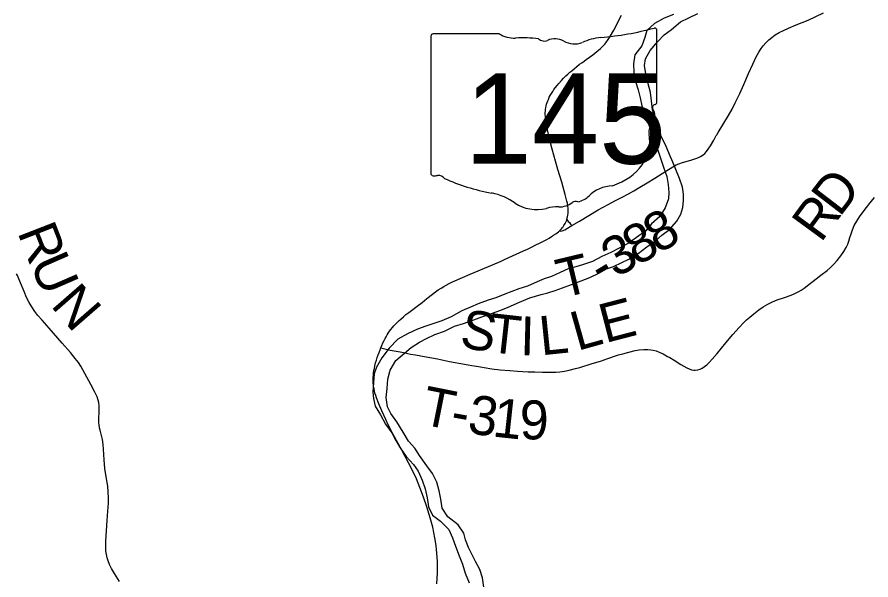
# Model space of a CAD drawing. Extents: x -10.5 to 40.6, y -3.2 to 22.
# Drawn here: x -8.513 to -7.268, y 15.194 to 16.014 of the extents above; entities that cross this region are included whole.
import ezdxf

# ---------------------------------------------------------------- set-up
doc = ezdxf.new("R2010")
doc.units = 0
for name, color, linetype in [('GM_X_Major_River', 7, 'Continuous'), ('GM_X_State_Location', 7, 'Continuous'), ('GM_X_State_Route', 7, 'Continuous'), ('GM_X_State_Shield', 7, 'Continuous'), ('GM_X_Township_Road', 7, 'Continuous'), ('GM_X_Township_Road_Text', 7, 'Continuous')]:
    doc.layers.add(name, color=color, linetype=linetype)

msp = doc.modelspace()

# ---------------------------------------------------------------- linework, layer by layer
at = {"layer": 'GM_X_Major_River'}
for points in [[(-7.5554, 16.0181), (-7.569, 16.0126), (-7.5833, 16.0052), (-7.5942, 15.9948), (-7.5971, 15.9846), (-7.6018, 15.9724), (-7.6119, 15.9593), (-7.6136, 15.9464), (-7.6134, 15.9335), (-7.611, 15.9203), (-7.607, 15.9082), (-7.6042, 15.8965), (-7.6018, 15.8851), (-7.597, 15.8719), (-7.5916, 15.8579), (-7.5872, 15.8451), (-7.5829, 15.8319), (-7.5785, 15.8202), (-7.5746, 15.8085), (-7.5699, 15.7957), (-7.5651, 15.7817), (-7.5634, 15.7703), (-7.5621, 15.7586), (-7.5628, 15.7491), (-7.5675, 15.7361), (-7.5753, 15.7235), (-7.5877, 15.7127), (-7.5959, 15.7027), (-7.6094, 15.6931), (-7.6203, 15.6853), (-7.6338, 15.678), (-7.647, 15.6709), (-7.6598, 15.6651), (-7.6738, 15.6577), (-7.6881, 15.6533), (-7.6979, 15.6501), (-7.7093, 15.647), (-7.7209, 15.6419), (-7.7334, 15.636), (-7.7439, 15.6325), (-7.7545, 15.6285), (-7.7684, 15.6219), (-7.7809, 15.6179), (-7.7911, 15.614), (-7.8016, 15.6104), (-7.8148, 15.6049), (-7.8258, 15.6014), (-7.8405, 15.5962), (-7.8518, 15.5912), (-7.8642, 15.5861), (-7.8797, 15.5771), (-7.8936, 15.5712), (-7.9053, 15.5673), (-7.9166, 15.5637), (-7.9291, 15.559), (-7.9434, 15.5524), (-7.9577, 15.5446), (-7.9704, 15.5315), (-7.9808, 15.5173), (-7.9886, 15.5039), (-7.9919, 15.494), (-7.9933, 15.4815), (-7.9942, 15.4675), (-7.9933, 15.458), (-7.9905, 15.447), (-7.9831, 15.4342), (-7.9754, 15.4207), (-7.9661, 15.4079), (-7.9603, 15.397), (-7.9541, 15.3864), (-7.9452, 15.3733), (-7.9348, 15.362), (-7.9278, 15.3519)], [(-7.9258, 15.375), (-7.9328, 15.3856), (-7.9421, 15.3961), (-7.9498, 15.4092), (-7.9591, 15.4239), (-7.968, 15.4363), (-7.9727, 15.4461), (-7.9748, 15.4594), (-7.973, 15.4727), (-7.9721, 15.4863), (-7.9689, 15.4993), (-7.9603, 15.5134), (-7.948, 15.5242), (-7.9382, 15.5323), (-7.9258, 15.5401), (-7.9156, 15.5455), (-7.9036, 15.5514), (-7.8896, 15.5565), (-7.8749, 15.5635), (-7.8617, 15.5675), (-7.8466, 15.573), (-7.8353, 15.5773), (-7.821, 15.5821), (-7.8074, 15.5868), (-7.7968, 15.5915), (-7.7803, 15.5986), (-7.7652, 15.6049), (-7.7486, 15.6096), (-7.7387, 15.612), (-7.7282, 15.6156), (-7.7176, 15.6195), (-7.7044, 15.6243), (-7.6904, 15.6298), (-7.6776, 15.6345), (-7.6644, 15.6407), (-7.6531, 15.647), (-7.643, 15.6505), (-7.6309, 15.6564), (-7.6207, 15.6614), (-7.6072, 15.6696), (-7.5944, 15.6792), (-7.5824, 15.6878), (-7.5723, 15.6962), (-7.5614, 15.7044), (-7.5506, 15.7166), (-7.545, 15.727), (-7.5421, 15.7365), (-7.5411, 15.7467), (-7.5409, 15.7562), (-7.5425, 15.7664), (-7.5469, 15.7789), (-7.5563, 15.803), (-7.5614, 15.814), (-7.5673, 15.8279), (-7.5735, 15.8404), (-7.5771, 15.8536), (-7.5814, 15.8657), (-7.5862, 15.8793), (-7.5875, 15.8921), (-7.5891, 15.9046), (-7.5931, 15.919), (-7.596, 15.9315), (-7.5976, 15.9436), (-7.5963, 15.9535), (-7.5896, 15.9657), (-7.5784, 15.9787), (-7.5691, 15.9884), (-7.5586, 15.9965), (-7.5454, 16.0073), (-7.533, 16.0131), (-7.5202, 16.0194)], [(-7.8323, 15.1828), (-7.834, 15.1965), (-7.8379, 15.2089), (-7.8445, 15.2206), (-7.8547, 15.2409), (-7.859, 15.2519), (-7.8614, 15.2617), (-7.8695, 15.2741), (-7.8848, 15.2857), (-7.893, 15.2981), (-7.8947, 15.3114), (-7.8971, 15.3235), (-7.9007, 15.3363), (-7.9069, 15.3488), (-7.9154, 15.36), (-7.9258, 15.375)], [(-7.9278, 15.3519), (-7.922, 15.3391), (-7.9176, 15.3266), (-7.9148, 15.313), (-7.9127, 15.3001), (-7.9072, 15.288), (-7.8954, 15.2791), (-7.8831, 15.2671), (-7.878, 15.2547), (-7.8733, 15.2426), (-7.8681, 15.2286), (-7.8634, 15.2165), (-7.8595, 15.2033), (-7.8536, 15.1894)]]:
    msp.add_lwpolyline(points, dxfattribs=at)
at = {"layer": 'GM_X_State_Route'}
for points in [[(-7.6543, 15.9769), (-7.653, 15.9785), (-7.6517, 15.9802), (-7.6497, 15.9833), (-7.6473, 15.987), (-7.6424, 15.9954), (-7.6393, 16.0015), (-7.6356, 16.0089), (-7.6315, 16.017)], [(-7.9005, 15.1878), (-7.8998, 15.2038), (-7.8997, 15.2149), (-7.8998, 15.2206), (-7.9001, 15.2266), (-7.901, 15.2377), (-7.9017, 15.2438), (-7.9034, 15.2548), (-7.9049, 15.2627), (-7.9067, 15.2705), (-7.9104, 15.2843), (-7.9153, 15.3003), (-7.9201, 15.3144), (-7.9253, 15.3283), (-7.9305, 15.3409), (-7.9356, 15.3522), (-7.9418, 15.3643), (-7.9518, 15.3829), (-7.965, 15.4068), (-7.9715, 15.4196), (-7.9752, 15.4274), (-7.9807, 15.4399), (-7.9852, 15.4502), (-7.9886, 15.459), (-7.9898, 15.4626), (-7.9909, 15.4661), (-7.9917, 15.4694), (-7.9923, 15.4722), (-7.9929, 15.4752), (-7.9932, 15.4777), (-7.9935, 15.4807), (-7.9936, 15.4834), (-7.9937, 15.4862), (-7.9935, 15.489), (-7.9933, 15.492), (-7.9929, 15.4952), (-7.9924, 15.4989), (-7.9918, 15.502), (-7.991, 15.5057), (-7.99, 15.5099), (-7.9889, 15.514), (-7.9877, 15.5177), (-7.9863, 15.522), (-7.985, 15.5254), (-7.9831, 15.5304), (-7.9824, 15.532), (-7.9811, 15.5352), (-7.9794, 15.5391), (-7.9777, 15.5426), (-7.9762, 15.5457), (-7.9748, 15.5482), (-7.9731, 15.551), (-7.9715, 15.5535), (-7.9697, 15.5561), (-7.9678, 15.5586), (-7.9655, 15.5615), (-7.9635, 15.5639), (-7.9611, 15.5666), (-7.9588, 15.5689), (-7.9555, 15.572), (-7.9533, 15.574), (-7.9494, 15.5773), (-7.9457, 15.5804), (-7.9415, 15.5837), (-7.9378, 15.5864), (-7.9294, 15.5929), (-7.9222, 15.5983), (-7.9155, 15.6039), (-7.9068, 15.6105), (-7.9026, 15.6136), (-7.8986, 15.6164), (-7.8943, 15.6192), (-7.8906, 15.6215), (-7.8869, 15.6235), (-7.8829, 15.6256), (-7.8778, 15.6281), (-7.8632, 15.6347), (-7.8523, 15.6394), (-7.8196, 15.653), (-7.8071, 15.6585), (-7.8008, 15.6613), (-7.7743, 15.6733), (-7.7686, 15.676), (-7.7625, 15.679), (-7.7563, 15.682), (-7.7509, 15.6848), (-7.7452, 15.6877), (-7.7404, 15.6902), (-7.7369, 15.6921), (-7.7334, 15.6942), (-7.7303, 15.6961), (-7.7273, 15.6983), (-7.7253, 15.6997), (-7.7234, 15.7013), (-7.7217, 15.7027), (-7.7203, 15.7042), (-7.7188, 15.7057), (-7.7174, 15.7073), (-7.7164, 15.7087), (-7.7153, 15.7103), (-7.7144, 15.7117), (-7.7135, 15.7134), (-7.7126, 15.7152), (-7.7118, 15.7173), (-7.7111, 15.7192), (-7.7105, 15.7214), (-7.7099, 15.7233), (-7.7096, 15.7255), (-7.7091, 15.7282), (-7.7089, 15.7306), (-7.7089, 15.7328), (-7.7091, 15.7358), (-7.7094, 15.7388), (-7.7102, 15.7429), (-7.7109, 15.746), (-7.7123, 15.7517), (-7.7134, 15.7556), (-7.7164, 15.7664), (-7.7186, 15.7735), (-7.7241, 15.792), (-7.7277, 15.8045), (-7.7323, 15.8219), (-7.7357, 15.8351), (-7.7394, 15.8501), (-7.741, 15.8574), (-7.7419, 15.863), (-7.7423, 15.8663), (-7.7424, 15.8692), (-7.7425, 15.8721), (-7.7425, 15.8749), (-7.7423, 15.8774), (-7.7421, 15.8799), (-7.7418, 15.8821), (-7.7412, 15.8849), (-7.7407, 15.8872), (-7.7399, 15.8897), (-7.739, 15.8922), (-7.738, 15.8944), (-7.7367, 15.8974), (-7.7352, 15.9), (-7.7336, 15.903), (-7.7317, 15.906), (-7.7299, 15.9086), (-7.7281, 15.9111), (-7.7251, 15.9147), (-7.7229, 15.9173), (-7.7188, 15.9218), (-7.7158, 15.9251), (-7.7123, 15.9286), (-7.7096, 15.9313), (-7.7065, 15.9341), (-7.704, 15.9362), (-7.7001, 15.9395), (-7.6963, 15.9425), (-7.6924, 15.9455), (-7.6893, 15.9477), (-7.6857, 15.9503), (-7.6827, 15.9525), (-7.6778, 15.9561), (-7.6733, 15.9594), (-7.6704, 15.9617), (-7.6675, 15.964), (-7.6647, 15.9663), (-7.6622, 15.9684), (-7.6594, 15.9711), (-7.657, 15.9736), (-7.6557, 15.9751), (-7.6543, 15.9769)]]:
    msp.add_lwpolyline(points, dxfattribs=at)
at = {"layer": 'GM_X_State_Shield'}
for p, q in [((-7.5797, 15.8903), (-7.5797, 15.995)), ((-7.9093, 15.9866), (-7.9093, 15.7865)), ((-7.8095, 15.99), (-7.9061, 15.99)), ((-7.5798, 15.8903), (-7.5797, 15.8903))]:
    msp.add_line(p, q, dxfattribs=at)
for centre, major_axis, start_param, end_param in [((-7.6971, 16.2629), (0.3495, 0), 4.814394, 5.042369), ((-7.5834, 15.9954), (0.00367, 0), 6.141152, 7.989035), ((-7.9055, 15.987), (0.00382, 0), 1.712693, 3.28349), ((-7.7866, 16.0133), (0.037, 0), 4.042523, 4.731795), ((-7.7743, 15.8777), (0.133, 0), 1.404758, 1.657858), ((-7.7441, 15.988), (0.0107, 0), 3.836095, 5.185415), ((-7.7284, 15.9649), (0.0222, 0), 0.950623, 2.079405), ((-7.6997, 15.9966), (0.0267, 0), 4.081561, 5.145723), ((-7.6525, 15.9289), (0.0703, 0), 1.699011, 2.107814), ((-7.5806, 15.8826), (0.00568, 0), 1.883978, 3.671073), ((-7.6167, 15.8694), (0.0341, 0), 5.934695, 6.695948), ((-7.5836, 15.8899), (0.00393, 0), 5.05454, 6.418171), ((-7.5666, 15.8465), (0.0248, 0), 2.387724, 3.262537), ((-7.6775, 15.8332), (0.0874, 0), 5.101752, 6.440018), ((-7.9055, 15.786), (0.00385, 0), 3.00124, 4.508301), ((-7.9049, 15.8065), (0.0294, 0), 4.665946, 4.897461), ((-7.8989, 15.7749), (0.0106, 0), 0.519207, 1.627899), ((-7.7651, 15.9547), (0.2524, 0), 4.195997, 4.488961), ((-7.6407, 15.7303), (0.0479, 0), 1.647645, 2.488434), ((-7.8403, 15.6966), (0.079, 0), 0.823519, 1.323587), ((-7.7549, 15.7739), (0.0501, 0), 4.026481, 4.996735), ((-7.7223, 15.7589), (0.0267, 0), 4.691044, 5.507374), ((-7.6981, 15.7396), (0.00752, 0), 1.147584, 2.315152), ((-7.7013, 15.7671), (0.0282, 0), 4.937069, 5.64225), ((-7.726, 15.7047), (0.0412, 0), 1.495662, 1.94098)]:
    msp.add_ellipse(centre, major_axis=major_axis, ratio=0.8, start_param=start_param, end_param=end_param, dxfattribs=at)
at = {"layer": 'GM_X_Township_Road'}
for points in [[(-7.7039, 15.7103), (-7.6928, 15.7169), (-7.679, 15.7252), (-7.6656, 15.7331), (-7.6509, 15.7412), (-7.641, 15.7464), (-7.6305, 15.7517), (-7.6213, 15.7568), (-7.6133, 15.7612), (-7.6045, 15.7663), (-7.5938, 15.7726), (-7.5827, 15.7794), (-7.5665, 15.7898), (-7.5565, 15.796), (-7.5542, 15.7974), (-7.5516, 15.7987), (-7.5476, 15.8004), (-7.5423, 15.8022), (-7.5304, 15.8057), (-7.5227, 15.8081), (-7.5192, 15.8095), (-7.516, 15.8113), (-7.5124, 15.8137), (-7.51, 15.8156), (-7.5074, 15.8183), (-7.5048, 15.8217), (-7.5017, 15.8264), (-7.4968, 15.835), (-7.4931, 15.8415), (-7.4925, 15.8425), (-7.4903, 15.8462), (-7.4752, 15.8711), (-7.47, 15.8803), (-7.4654, 15.8891), (-7.4589, 15.9031), (-7.4531, 15.9162), (-7.4462, 15.9321), (-7.4399, 15.9456), (-7.4347, 15.9562), (-7.4308, 15.9632), (-7.4274, 15.9685), (-7.4245, 15.9724), (-7.4208, 15.9767), (-7.4164, 15.9811), (-7.4122, 15.9847), (-7.4071, 15.9884), (-7.4013, 15.9919), (-7.3952, 15.995), (-7.3879, 15.9983), (-7.3764, 16.003), (-7.3591, 16.0101), (-7.3365, 16.0204)], [(-7.7466, 15.4965), (-7.7361, 15.4963), (-7.7269, 15.4966), (-7.7213, 15.4971), (-7.7145, 15.4979), (-7.7078, 15.4992), (-7.6982, 15.5017), (-7.6922, 15.5034), (-7.6739, 15.5091), (-7.6621, 15.5128), (-7.6515, 15.5164), (-7.6385, 15.5207), (-7.6355, 15.5217), (-7.6296, 15.5234), (-7.6206, 15.5258), (-7.6115, 15.5279), (-7.6054, 15.5289), (-7.5986, 15.5295), (-7.593, 15.5296), (-7.5887, 15.5292), (-7.585, 15.5286), (-7.5808, 15.5276), (-7.5762, 15.5259), (-7.5706, 15.5232), (-7.5641, 15.5196), (-7.5609, 15.5177), (-7.5545, 15.514), (-7.5446, 15.5079), (-7.5361, 15.5028), (-7.5328, 15.5012), (-7.5293, 15.4999), (-7.5257, 15.4993), (-7.5239, 15.4993), (-7.5202, 15.4997), (-7.5167, 15.5009), (-7.5139, 15.5022), (-7.5103, 15.5046), (-7.5069, 15.5074), (-7.5033, 15.5108), (-7.4991, 15.5154), (-7.4918, 15.5239), (-7.4792, 15.5392), (-7.4688, 15.5515), (-7.4597, 15.5617), (-7.4533, 15.5684), (-7.4489, 15.5727), (-7.4442, 15.5768), (-7.4385, 15.5816), (-7.4312, 15.5872), (-7.4245, 15.5917), (-7.4177, 15.5958), (-7.411, 15.5991), (-7.4041, 15.6019), (-7.3935, 15.6056), (-7.3841, 15.6088), (-7.3784, 15.6112), (-7.3729, 15.614), (-7.3691, 15.6162), (-7.365, 15.6189), (-7.3581, 15.6242), (-7.3473, 15.6326), (-7.3405, 15.6379), (-7.3315, 15.6446), (-7.3263, 15.649), (-7.3215, 15.6538), (-7.3166, 15.6595), (-7.3113, 15.6663), (-7.3071, 15.6724), (-7.3036, 15.6783), (-7.3012, 15.6833), (-7.2998, 15.6874), (-7.2981, 15.6928), (-7.2965, 15.6981), (-7.2945, 15.704), (-7.2918, 15.7103), (-7.2883, 15.7169), (-7.2842, 15.7232), (-7.2804, 15.7285), (-7.277, 15.7329), (-7.2744, 15.7362), (-7.2717, 15.7396), (-7.271, 15.7406), (-7.2625, 15.7511)], [(-7.7111, 15.7192), (-7.7089, 15.7165), (-7.7073, 15.7147), (-7.7055, 15.7123), (-7.7039, 15.7103)], [(-7.7217, 15.7027), (-7.7196, 15.7024), (-7.7179, 15.7026), (-7.7142, 15.7043), (-7.7062, 15.709), (-7.7039, 15.7103)], [(-8.3635, 15.1914), (-8.3709, 15.2029), (-8.3753, 15.2104), (-8.3781, 15.216), (-8.3802, 15.2212), (-8.3817, 15.2259), (-8.3827, 15.2307), (-8.3833, 15.2357), (-8.3837, 15.2419), (-8.3836, 15.25), (-8.3816, 15.2803), (-8.3804, 15.2939), (-8.3796, 15.3056), (-8.3795, 15.3131), (-8.3799, 15.3218), (-8.3808, 15.3304), (-8.3829, 15.3439), (-8.3849, 15.3562), (-8.3856, 15.3623), (-8.386, 15.3685), (-8.3868, 15.384), (-8.3874, 15.3908), (-8.3885, 15.3982), (-8.3916, 15.4121), (-8.3925, 15.4153), (-8.3934, 15.4196), (-8.3936, 15.4226), (-8.3939, 15.4263), (-8.3936, 15.4316), (-8.3931, 15.4361), (-8.393, 15.4423), (-8.393, 15.4473), (-8.3935, 15.4522), (-8.3945, 15.4557), (-8.3962, 15.4604), (-8.4, 15.4682), (-8.4053, 15.4787), (-8.4139, 15.4945), (-8.4201, 15.5052), (-8.4236, 15.5104), (-8.428, 15.5164), (-8.4351, 15.525), (-8.4474, 15.539), (-8.4662, 15.5606), (-8.4765, 15.5722), (-8.4825, 15.5793), (-8.4869, 15.5852), (-8.4914, 15.5919), (-8.4953, 15.5983), (-8.499, 15.6055), (-8.5028, 15.614), (-8.5078, 15.6267), (-8.5114, 15.6352), (-8.5124, 15.6375), (-8.5136, 15.6397)], [(-7.9824, 15.532), (-7.9705, 15.5292), (-7.9688, 15.5288), (-7.9542, 15.526), (-7.9469, 15.5245), (-7.939, 15.523), (-7.9316, 15.5216), (-7.9164, 15.5189), (-7.9078, 15.5173), (-7.8999, 15.5158), (-7.8824, 15.5122), (-7.8739, 15.5106), (-7.8684, 15.5096), (-7.8551, 15.5072), (-7.8496, 15.5063), (-7.843, 15.5052), (-7.8369, 15.5042), (-7.8315, 15.5034), (-7.8207, 15.5016), (-7.8084, 15.5001), (-7.7942, 15.4989), (-7.7829, 15.4978), (-7.7676, 15.4971), (-7.7579, 15.4968), (-7.7466, 15.4965)]]:
    msp.add_lwpolyline(points, dxfattribs=at)

# ---------------------------------------------------------------- texts
at = {"layer": 'GM_X_State_Location'}
for s in ['s', 'r']:
    msp.add_text(s, height=0.000189, dxfattribs=at).set_placement((-7.7482, 15.8732))
msp.add_text('145', height=0.000189, rotation=0, dxfattribs=at).set_placement((-7.8151, 15.8594))
at = {"layer": 'GM_X_State_Shield'}
msp.add_text('145', height=0.13184, dxfattribs=at).set_placement((-7.8602, 15.8006))
at = {"layer": 'GM_X_Township_Road_Text'}
for s, rotation, p in [('D', 52.5822, (-7.3133, 15.7214)), ('R', 53.8162, (-7.3406, 15.684)), ('8', 30.3099, (-7.578, 15.6683)), ('R', 291.2267, (-8.5129, 15.7009)), ('8', 29.606, (-7.6091, 15.6506)), ('3', 29.4731, (-7.6397, 15.6334)), ('U', 293.5152, (-8.4951, 15.6552)), ('T', 13.4739, (-7.7182, 15.6043)), ('-', 31.269, (-7.6592, 15.6215)), ('N', 311.0863, (-8.4652, 15.5936)), ('E', 14.5913, (-7.6552, 15.5387)), ('S', 350.0917, (-7.8689, 15.5334)), ('T', 353.7066, (-7.8273, 15.5262)), ('L', 15.7141, (-7.6958, 15.5273)), ('I', 358.6214, (-7.7797, 15.5212)), ('L', 5.8729, (-7.7485, 15.521)), ('T', 348.685, (-7.9257, 15.4211)), ('3', 352.0843, (-7.8574, 15.4079)), ('1', 353.7955, (-7.8209, 15.4029)), ('9', 359.4827, (-7.78, 15.3987)), ('-', 349.7172, (-7.8829, 15.4125))]:
    msp.add_text(s, height=0.0568, rotation=rotation, dxfattribs=at).set_placement(p)

doc.saveas('drawing.dxf')
